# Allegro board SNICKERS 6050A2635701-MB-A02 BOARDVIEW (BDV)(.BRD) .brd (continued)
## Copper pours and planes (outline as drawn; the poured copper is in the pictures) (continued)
SD_MMC_DATA2 on BOTTOM: 299.12,73.52 299.24,73.65 299.24,74.79 298.99,75.04 297.09,75.04 296.83,74.79 296.83,73.77 297.09,73.52
SD_MMC_WP on BOTTOM (solid shape): 299.63,53.71 299.5,53.58 297.09,53.58 296.96,53.71 296.96,53.83 297.34,54.21 299.24,54.21 299.5,54.47 299.63,54.47
UIM_PWR on TOP: 257.08,80 258.99,80 259.24,79.74 259.24,78.73 258.99,78.47 258.1,78.47 257.72,78.09 257.72,75.8 257.33,75.42 255.05,75.42 254.79,75.68 254.79,76.44 255.18,76.82 255.18,79.49 255.43,79.49 255.81,79.87 256.95,79.87
UNNAMED_5_CHOKE2PIN_I90_INB on BOTTOM (solid shape): 273.84,132.57 273.84,131.56 274.61,131.56 274.61,132.57 275.5,132.57 275.75,132.32 275.75,129.02 275.37,128.64 271.18,128.64 270.8,129.02 270.8,132.19 271.56,132.95 273.46,132.95
UNNAMED_5_NMOS4D3S_I34_D0 on TOP (solid shape): 290.48,142.61 292.51,142.61 292.64,142.48 292.64,138.67 292.26,138.29 290.99,138.29 290.74,138.03 288.83,138.03 288.32,138.54 288.32,138.92 289.59,138.92 289.59,139.69 288.32,139.69 288.32,140.07 288.58,140.32 288.58,142.86 290.23,142.86
UNNAMED_7_CSC0805_I17_A on BOTTOM: 241.04,147.02 240.44,146.42 238.5,146.42 238.18,146.73 238.18,148.12 238.39,148.12 238.57,147.93 238.57,147.78 238.79,147.55 240.11,147.55 241,148.45 242.73,148.45 243.75,149.46 246.41,149.46 246.67,149.21 246.67,148.58 246.16,148.07 246.16,146.67 246.03,146.54 244.63,146.54 244.16,147.02
UNNAMED_7_CSC0805_I24_A on BOTTOM: 206.66,154.29 209.46,154.29 209.84,153.91 212.5,153.91 212.88,154.29 212.88,155.05 212.63,155.31 211.11,155.31 210.47,155.94 206.28,155.94 205.24,154.9 204.78,154.9 204.78,154.7 206.25,154.7
UNNAMED_9_AOZ1268QI02_I10_22 on BOTTOM: 154.82,162.37 154.92,162.27 154.92,161.22 154.51,161.22 154.51,158.56 154.92,158.56 154.92,157.74 155.25,157.74 155.25,158.56 155.84,158.56 155.84,161.78 155.99,161.94 155.99,163.31 155.81,163.48 146.01,163.48 145.57,163.05 145.57,161.28 145.83,161.02 146.97,161.02 147.35,160.64 151.16,160.64 151.67,161.15 151.67,161.4 152.31,162.04 153.96,162.04 154.29,162.37
UNNAMED_9_CSC0402_I67_A on BOTTOM: 176.31,152.08 177.63,152.08 177.96,151.75 178.85,151.75 179.36,151.24 179.36,150.48 179.1,150.23 178.85,150.23 178.34,150.73 177.83,150.73 177.71,150.61 176.82,150.61 176.56,150.86 176.56,151.5 176.31,151.75
UNNAMED_10_AOZ1268QI02_I13_22 on BOTTOM: 126.02,101.08 125.76,100.82 124.75,100.82 124.37,100.44 124.37,100.19 124.24,100.06 124.24,96.78 123.65,96.78 123.65,96.07 123.32,96.07 123.32,96.78 122.92,96.78 122.92,99.48 123.32,99.48 123.32,100.95 123.35,100.95 123.6,101.2 123.6,101.84 124.24,102.47 124.24,103.62 124.75,104.13 125.76,104.13 126.02,103.87
UNNAMED_11_CSC0603_I5_A on TOP (solid shape): 107.22,148.58 107.22,146.42 107.09,146.29 106.2,146.29 105.57,145.65 104.17,145.65 103.77,145.25 101.48,145.25 101.48,148.55 101.76,148.83 106.97,148.83
UNNAMED_12_CSC0603_I5_A on TOP (solid shape): 249.84,84.95 250.6,84.95 250.73,84.82 250.73,83.42 251.24,82.92 251.24,82.03 250.48,82.03 250.22,82.28 250.22,82.54 249.84,82.92 248.95,82.92 248.83,83.04 248.83,83.93 248.7,84.06 247.94,84.06 247.68,84.31 247.68,85.33 249.46,85.33
UNNAMED_14_CSD97374CQ4M_I37_4 on BOTTOM (solid shape): 235.18,69.2 235.74,69.2 235.92,69.02 235.92,67.02 235.82,66.91 234.98,66.91 234.09,66.03 233.97,66.03 233,65.06 232.39,65.06 231.81,65.64 231.81,67.25 231.97,67.41 234.23,67.41 234.23,68.05 232.06,68.05 232.06,68.06 231.81,68.31 231.81,69.33 232,69.52 234.86,69.52
UNNAMED_16_2DC3092000111F_I111_ on TOP: 316.26,148.32 316.67,147.91 316.67,141.41 316.34,141.08 314.87,141.08 314.23,141.72 313.09,141.72 312.58,141.21 307.5,141.21 307.5,142.89 307.78,142.89 308.26,143.37 308.26,145.48 309.32,146.54 311.94,146.54 312.96,147.56 315.12,147.56 315.88,148.32
UNNAMED_46_5023802471001_I1031_ on TOP (solid shape): 111.03,148.19 111.03,147.18 110.9,147.05 109.76,147.05 109.63,147.18 109.63,148.19 109.76,148.32 110.9,148.32
VADPBL on TOP (solid shape): 297.09,138.92 296.96,138.8 293.53,138.8 293.1,139.23 293.1,141.21 294.29,141.21 294.55,141.46 294.55,142.23 294.93,142.61 297.09,142.61
VRP1V2A on TOP (solid shape): 255.56,90.28 255.56,86.98 256.95,85.58 256.95,84.06 257.59,83.42 257.59,82.92 257.33,82.66 254.54,82.66 254.41,82.79 254.41,83.17 254.67,83.42 254.67,84.82 254.29,85.2 253.52,85.2 253.14,85.58 253.14,90.16 253.52,90.54 255.3,90.54
VRP1V2A_PH on TOP (solid shape): 252.13,90.16 252.13,85.58 251.75,85.2 250.1,85.2 249.97,85.33 249.97,86.6 248.95,87.62 247.68,87.62 247.68,89.39 248.83,90.54 251.75,90.54
VRP1V05A on BOTTOM: 137.07,92.7 136.94,92.57 135.8,92.57 134.91,91.68 134.27,91.68 133.89,92.06 132.75,92.06 132.49,92.31 132.49,100.19 133.13,100.82 136.94,100.82 137.07,100.7
VRP1V05A_PH on BOTTOM (solid shape): 130.33,95.74 130.08,95.49 126.02,95.49 125.64,95.87 125.38,95.87 125.33,95.92 125.33,96.68 125.13,96.89 124.64,96.89 124.64,99.86 124.82,99.86 124.82,100.24 125.66,100.24 125.66,99.71 125.56,99.6 125.56,97.7 125.74,97.52 127.16,97.52 127.79,98.16 127.79,99.55 128.81,100.57 130.33,100.57
VRP1V5S on BOTTOM (solid shape): 104.3,138.42 104.3,136.26 103.92,135.88 98.08,135.88 97.57,136.38 96.3,136.38 95.92,136.76 95.92,138.67 96.68,139.43 103.28,139.43
VRP1V5S_PH on TOP (solid shape): 99.09,148.58 99.09,146.85 99.24,146.7 99.24,145.22 96.35,145.22 95.66,145.91 95.66,148.58 95.92,148.83 98.84,148.83
VRP1V5S_PH on BOTTOM: 96.43,140.45 95.66,141.21 95.66,147.81 96.04,148.19 98.2,148.19 98.58,147.81 98.58,145.02 98.97,144.64 100.11,144.64 101.89,142.86 101.89,140.83 101.51,140.45
VRP3V3A on BOTTOM: 196.46,153.25 193.44,150.23 192.5,150.23 192.01,150.71 190.77,150.71 190.49,150.43 189.44,150.43 189.01,150.86 189.01,157.59 189.52,158.1 196.12,158.1 196.46,157.76
VRP3V3A_PH on BOTTOM: 199.28,156.83 199.28,153.2 199.58,152.89 202.22,152.89 202.98,153.66 204.4,153.66 204.4,154.54 203.11,154.54 202.22,155.43 202.22,156.58 201.71,157.08 199.53,157.08
VRP5V0A on BOTTOM: 237.27,156.45 237.27,152.54 236.96,152.24 233.05,152.24 232.57,151.75 232.57,150.23 232.32,149.97 229.01,149.97 228.81,150.17 228.81,153.23 226.09,155.95 226.09,158.54 227.11,159.56 228.33,159.56 228.93,158.95 228.93,158.92 230.54,158.92 232.25,157.21 236.89,157.21 237.27,156.83 237.27,156.45
VRP5V0A_PH on BOTTOM: 237.9,156.83 237.9,152.26 237.02,151.37 237.02,148.63 237.21,148.44 238.12,148.44 238.31,148.64 238.31,150.01 240.31,152 242.98,152 242.98,156.58 242.35,157.21 238.28,157.21
VRPVDDQ on BOTTOM (solid shape): 166.78,159.12 166.78,151.37 167.42,150.73 167.42,149.95 167.42,149.59 167.16,149.34 166.53,149.34 165.89,149.97 164.5,149.97 163.1,151.37 163.1,158.61 163.11,158.66 163.11,158.75 163.61,159.24 166.66,159.24
VRPVDDQ_PH on BOTTOM: 157.31,159.32 159.72,159.32 160.94,158.1 160.94,152.89 160.05,152 157.77,152 157,152.77 157,157.59 156.9,157.69 156.9,158.48 156.78,158.61 156.22,158.61 156.22,161.61 156.45,161.61 156.45,162.04 157.26,162.04 157.26,161.78 157.13,161.66 157.13,159.5
VRPVPACK_HG on BOTTOM (solid shape): 272.96,122.79 272.96,122.41 272.35,121.8 271.56,121.8 271.56,122.79 271.69,122.92 272.83,122.92
VRPVPACK_LG on TOP (solid shape): 286.42,125.72 285.66,124.95 285.02,124.95 285.02,125.72 285.27,125.72 285.78,126.22 285.78,126.48 286.42,126.48
VRPVPACK_PH on BOTTOM (solid shape): 269.59,125.91 275.3,125.91 275.62,125.59 275.62,119.37 275.37,119.11 274.99,119.11 274.73,119.37 273.34,119.37 272.96,119.75 272.96,122.03 273.21,122.29 273.21,122.92 272.83,123.3 271.69,123.3 271.3,122.92 271.3,121.8 269.63,121.8 269.59,121.84 269.08,121.84 268.51,122.41 268.51,125.59 268.89,125.97 269.53,125.97
VRPVTT on BOTTOM: 170.72,155.81 173.22,155.81 173.56,155.48 173.56,154.76 173.85,154.46 173.85,153.78 172.2,153.78 172.05,153.63 172.05,153.2 172.18,153.07 174.07,153.07 174.07,152.74 171.99,152.74 171.99,152.77 171.61,153.15 171.36,153.15 170.72,153.78 170.47,153.78 170.47,155.56
VRPVTT_REF on BOTTOM (solid shape): 182.91,153.66 182.91,152.26 182.79,152.13 182.53,152.13 182.02,152.64 181.64,152.64 181.52,152.77 181.52,154.54 182.02,154.54

Small or netless copper shapes (teardrops, artwork), in the pictures only: 1705 on TOP, 2506 on BOTTOM, 1708 on L3, 12 on L4, 1544 on L5, 1993 on L6

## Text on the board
Ref Des/Silkscreen Bottom: -PICKBUTTONB-A01 | 6050A2630801 | FAN | 6050A2631001 | -MIC-A01 | SPK | DIMM2 | M2X3 | HSTNN-I29C | DIMM1 | WWAN | Flash cache | WLAN | 6050A2635501-SMARTCARD-A01
Ref Des/Silkscreen Top: KB Backlit | M2x1.5 | SMART | POWER | PS | RTC | KB | FPR
User.9: HCI1005F_R12J_M | 0.1uF_16V_2_DY | short_0402_15 | 1uF_6.3V_2_DY | 680pF_50V_2_DY | 0.1uF_25V_2_DY | SFI_SFI0603_240E2R5PP_LF_2P | 0.22uF_6.3V_2 | SFI0402_050E3R0PP_LF_DY | 2.2uF_6.3V_2_DY | 0.022uF_16V_2 | 68pF_50V_2_DY | 82pF_50V_2_DY | PANASONIC_DB3X313J0L_SOT_3P | RICHTEK_RT8068AZQW_WDFN_10P | PANASONIC_DB3X313J0L_SOT_3P_DY | OSRAM_NL27WZ07DFT2G_SC88_6P | 100pF_50V_2_DY | 6.04K_1%_1/16W_2 | TSB_TC7SZ07FU_SSOP_5P | ROHM_BD82034FVJ_GE2_MSOP_8P | 18pF_50V_2_DY | 0.068uF_10V_2 | PHP_PESD5V2S2UT_SOT23_3P_DY | SFI0402_050E3R0PP_LF | 0.047uF_16V_2 | PHP_PESD5V0S1BB_SOD523_2P | EVL_12_22_Y2ST3D_C30_2C_3P | EVL_12_21_T3D_CP1Q2B12Y_2C_2P | 17.8K_1%_2 | GMT_G708T1U_SOT23_5P | LES_LBSS84LT1G_SOT23_3P | 0.1uF_16V_2 | 0.01uF_50V_2 | 1000PF_50V_2 | 100K_5%_2_DY | 10K_5%_2_DY | 1uF_6.3V_2 | CSC0402_DY | short_0402_5 | short_0603_25 | 82pF_50V_2 | 0.1uF_25V_2 | 2.2uF_6.3V_2 | 4.7uF_6.3V_3_DY | 2.2K_5%_2_DY | 8.2K_5%_2_DY | 10uF_6.3V_3_DY | 1K_1%_2_DY | 51_5%_2_DY | 47pF_50V_2 | 1K_5%_2_DY | L2N7002WT1G_DY | ON_LMV393DMR2G_SOP_8P | 10K_1%_2_DY | 68pF_50V_2 | 2200pF_50V_2 | POWERPAD1x1m | 330K_5%_2_DY | 47K_5%_2_DY | DIODE-BAT54-TAP-PHP_DY | 8.66K_1%_2 | 45.3K_1%_2 | 39.2K_1%_2 | 10pF_50V_2 | RSC_0402_DY | 3.01K_1%_2 | EVL_23_22B_Y2ST3D_C30_2T_4P | 22K_5%_2_DY | 100pF_50V_2 | 0.01uF_100V_3 | 1M_5%_2_DY | 12pF_50V_2 | 3.24K_1%_2 | 3900pF_16V_2 | 15pF_50V_2 | NUVO_NCT3521U_SOT23_5P | 57.6K_1%_2 | 31.6K_1%_2 | 0.15uF_10V_2 | 13.7K_1%_2 | 3300pF_50V_2 | ST_HP3DC2TR_LGA_16P | 53.6K_1%_2 | 16.2K_1%_2 | 41.2K_1%_2 | 51.1K_1%_2 | 38.3K_1%_2 | 46.4K_1%_2 | 35.7K_1%_2 | 4.7K_5%_2_DY | 18.2K_1%_2 | 49.9K_1%_2 | 86.6K_1%_2 | ALPHA_AO6424L_TSOP_6P | 3.48K_1%_2 | 22UF_6.3V_3_DY | PANJTT_PJSOT24C_SOT23_3P | 20K_5%_2 | 4.7K_5%_2 | 470_5%_2 | 0_5%_2_DY | 270_5%_2 | 10K_5%_2 | 10uF_6.3V_3 | 100_5%_2 | 10K_1%_2 | 15K_1%_2 | 4.7uF_6.3V_3 | 100K_5%_2 | L2N7002WT1G | 22.6_1%_2 | 8.2K_5%_2 | 22uF_6.3V_5_DY | 1.8K_1%_2 | 49.9_1%_2 | 24.9_1%_2 | L2N7002DW1T1G | 200K_5%_2 | 110_1%_2 | 150_5%_2 | 64.9_1%_2 | 0.33uF_10V_3 | POWERPAD_2_0610 | 2.2K_5%_2 | ENTERY_3703K_Q02N_11L_2P | SWF2520CF_4R7K_M | 300_5%_2 | 6.2K_1%_2 | 13K_1%_2 | 4.3K_5%_2 | REALTEK_RTS5237_GR_QFN_32P | RSC_0603_DY | 2.2uF_6.3V_3 | 22K_5%_2 | MISAKI_NTC011_BA1J_A160T_4P | HP_HPA022642RTJ_QFN_20P | BLM18PG600SN1D | 39K_1%_2 | 150_1%_2 | 2.1K_1%_2 | 619_1%_2 | 47K_5%_2 | 1.2K_1%_2 | 330_5%_2 | 470K_5%_2 | 100_1%_2 | 3.3K_5%_2 | 3.3K_1%_2 | 11K_1%_2 | 12K_1%_2 | 1uF_10V_2 | ALPHA_AON7403L_DFN_8P | TI_BQ24736RGRR_QFN_20P | 20K_1%_2 | 200K_1%_2 | 576K_1%_2 | 330K_5%_2 | 5.1K_1%_2 | 274K_1%_2 | 130K_1%_2 | 220K_5%_2 | LMBT3904LT1G | 1K_5%_2 | 33_5%_2 | 0_5%_2 | 2K_5%_2 | WCM_2012_900T | 127K_1% | 2.2uH_20% | 22uF_6.3V_5 | 2_1%_2 | 51_5%_2 | 75_1%_2 | 56_5%_2 | 62_5%_2 | AZV331KTR_E1 | DIODES_BAV99 | BAT54_30V_0.2A | INTEL_CLARKVILLE_I218_LM_48P | 30_5%_2 | BZT52-B4V7S_DY | 22_5%_2 | 10_5%_2 | 43_5%_2 | 1M_5%_2 | 1K_1%_2 | 1uF_25V_3 | 47_5%_2 | 1SS355VMTE_17 | RQ3E080BNFU7TB | REALTEK_ALC3228_CG_QFN_48P | RQ3E100BNFU7TB | PDTC144EU | ALCOR_AU9560B62_GBS_GR_SSOP_28P | TP24 | NXP_PTN3355BS_HVQFN_40P | BSS138LT1 | NRS5020T1R0NMGJ | STDPAD_3.15_5.5_TOP | SMSC_USB5534B_6080JZX_QFN_64P | PM513BA_DY | FDC638APZ | NFE31PT222Z1E9L | FIX_MASK | 100uF_6.3V | PMBT3906 | MMBT4401 | 330uF_2.5V_DY | ENTERY_6712K_F08M_02L_8P | 25MHz_10pF | BAW56S | 27MHz_10pF | 0_5%_3 | SCREW230_600_NP_1P | 10_5%_5 | SINGA_2SJ3005_023111F_7P | TP40 | ACES_50505_0064N_001_6P | BAT54C | 0.01_1%_6 | PM513BA | SCREW300_800_NP_1P | 330uF_2.5V | 100PF_3000V | 0_5%_5 | ACES_51548_01541_001_15P | B0530W_7 | ACES_50501_0184N_001_18P | 10k_5% | SINGA_2UB4006_180101F_9P | SAMTEC_BSH_030_01_L_D_A_TR_60P | BOTH_NA0069RLF_SMD_24P | TAIWIN_DP004_206CRL_TW_20P | FOX_JM3611_SP51AB11_7H_12P | ACES_51540_04041_001_40P | TAI_PMPAT3_08GLBS7N14N0_9P | ACES_51510_0344N_001_34P | SMSC_MEC1324_TQFP_128P
User.10: ROHM_BD82034FVJ_GE2_MSOP_8P | 0.1uF_16V_2_DY | 0.01uF_50V_2_DY | BLM15BB470SS1_DY | 2.2uF_6.3V_2_DY | BLM15BB470SN1D | SFI0402_050E3R0PP_LF | SFI_SFI0603_240E2R5PP_LF_2P | PHP_PESD5V0S1BB_SOD523_2P_DY | 68pF_50V_2_DY | 82pF_50V_2_DY | 10pF_50V_2_DY | short_0402_15 | 220pF_50V_2_DY | BLM15AG121SN1D_500mA | BCD_AH9249NTR_G1_TSOT23_3P | 1uF_6.3V_2_DY | SMSC_EMC1412_1_ACZL_TR_MSOP_8P | 0.1uF_25V_2_DY | SFI0402_050E3R0PP_LF_DY | 0.0015uF_50V_2 | 0.033uF_16V_2 | 0.1uF_16V_2 | 1uF_6.3V_2 | 0.01uF_50V_2 | ALPHA_AO6424L_TSOP_6P | 0.1uF_25V_2 | CSC0402_DY | short_0402_5 | 10K_5%_2_DY | 100pF_50V_2 | 8.2K_5%_2_DY | 18pF_50V_2 | 100K_5%_2_DY | 2.2uF_6.3V_2 | 4.7uF_6.3V_3_DY | 330K_5%_2_DY | 15pF_50V_2 | 1000PF_50V_2 | 2.05K_1%_2 | 3.01K_1%_2 | 10K_1%_NTC | RSC_0402_DY | 82pF_50V_2 | MXIC_MX25L1606EM2I_12G_SOP_8P_DY | 19_217_W1D_AP1Q2QY_3T | 4.7K_5%_2_DY | 68pF_50V_2 | TEXAS_TPS2546RTER_QFN_16P | 6.49K_1%_2 | 88.7K_1%_2 | ALPHA_OMEGA_AOZ1268QI_02_QFN_23P | POWERPAD_2_0610_DY | TSB_TC7SH17F_SSOP_5P | POWERPAD1x1m | GMT_G2997RE1U_TDFN_10P | POWERPAD1x1m_DY | KNOWLES_SPK0415HM4H_B_8P | 18.7K_1%_2 | 4700pF_50V_2 | 1.02M_1%_2 | 100K_1%_NTC | 9.31K_1%_2 | 220K_5%_2_DY | 4.99K_1%_2 | TI_TLV2462CDGKR_MSOP_8P | 220pF_50V_2 | 0_5%_2_DY | 10K_5%_2 | 4.7uF_6.3V_3 | L2N7002WT1G | 2.2K_5%_2 | L2N7002DW1T1G | POWERPAD_2_0610 | RSC_0603_DY | 22uF_6.3V_5_DY | 10uF_6.3V_3 | 100K_5%_2 | 33K_5%_2 | 20K_5%_2 | WINB_W25Q128FVSIQ_SOIC_8P | 470_5%_2 | 14K_1%_2 | 20K_1%_2 | 200K_5%_2 | 8.2K_5%_2 | DIODES_DMG3414U_7 | 43K_1%_2 | 330K_5%_2 | MPS_NB670GQ_QFN_16P | 0.22uF_25V_3 | 10K_1%_2 | 1uF_10V_2 | MISAKI_NTC011_BA1J_A160T_4P | 4.7K_5%_2 | 100_5%_2 | BLM18PG600SN1D | 5.1M_5%_2 | 12K_5%_DY | 470K_5%_2 | 220_5%_2 | 47K_5%_2 | 3.3K_5%_2 | 64.9_1%_2 | 680_5%_2 | 10M_5%_2 | 24.9_1%_2 | 2.2uF_10V_3 | 100_1%_2 | 200_1%_2 | 120_1%_2 | 39K_1%_2 | 2.32K_1% | 54.9_1%_2 | 432K_1%_2 | TEXAS_TPS51622ARSMR_VQFN_32P | 100K_1%_2 | 110_1%_2 | 150K_1%_2 | TI_CSD97374CQ4M_SON_8P | MPS_NB676AGQ_QFN_16P | 22UF_6.3V_3 | 0_5%_2 | 22_5%_2 | 47_5%_2 | 2.2_5%_3 | 10UF_25V_5 | 22uF_6.3V_5 | 1K_5%_2 | 15_5%_2 | 1M_5%_2 | 33_5%_2 | 2.2uH_20% | LMBT3904LT1G | WINBOND_W25Q16DVSSIG_8P | 10_5%_2 | STDPAD_3.15_5.5_TOP | CSC0805_DY | TC7SZ08FU | 1uF_25V_3 | RQ3E100BNFU7TB | RQ3E150BNFU7TB | 3K_1%_2 | 4.7uF_25V_5 | DIODES_BAV99 | WCM_2012_900T | FDC638APZ_DY | INFINEON_SLB9660TT1_2_TSSOP_28P | TP24 | ACES_50376_01001_001_10P | NRS5020T1R0NMGJ | PARADE_PS8338AQFN60GTR_QFN_60P | SCREW280_500_NP_1P | FIX_MASK | SCREW230_600_NP_1P | PAN_ETQP3W1R0WFN_4P | STDPAD_1.15_6-TOP | SCREW230_500_1P | 24MHz_12pF | SCREW300_800_NP_1P | FDMC7692S | ACES_91960_0084L_8P | SCREW330_600_1P | PCME063T-R24MS1R195 | SCREW230_600_1P | FDMC8884 | PM514BA | ACES_50271_0040N_001_4P | BAT54C | SCREW360_800_NP_1P | 0_5%_5 | 0.02_1%_6 | SCREW300_800_1P | SCREW360_800_1P | PCMC063T-1R5MN | 15uF_25V | ACES_50238_02471_001_24P | SINGA_2DC3092_000111F_9P | ETQP3W4R7WFN | ALLTOP_C11848_122A1_L_22P | FOX_BP02083_B24B1_9H_8P | FOX_AS0A626_U4R6_7H_HP_204P | 32.768KHZ | 100uF_6.3V | INTEL_CL8064701477702_SR170_1168P | SYN_070546HR015M22BZR_15P | HAMB_083AA24F08B_10P | ACES_59003_04006_001_40P | LOTES_APCI0018_P005A_75P | LOTES_APCI0020_P001A01_75P | FOXCONN_AS0BC26_S30BE_7H_75P | FULLINHOPE_A0131_0001_12P | FOX_QL1046L_D262AR_7H_92P
User.45: FIGURE | SIZE | 10.0 | 12.0 | 16.0 | 20.0 | 24.0 | 27.0 | 28.0 | 31.0 | 35.0 | 39.0 | 45.0 | 91.0 | 118.0 | 124.0 | 130.0 | 142.0 | 25.0 | 33.0 | 40.0 | 43.0 | 46.0 | 49.0 | 51.0 | 63.0 | 110.0 | 158.0 | 45.0x26.0 | 47.0x28.0 | 55.0x26.0 | 63.0x16.0 | 63.0x24.0 | 67.0x28.0 | 73.0x31.0 | 79.0x24.0 | 83.0x28.0 | 87.0x20.0 | 94.0x24.0 | 100.0x28.0 | 102.0x31.0 | 106.0x39.0 | 63.0x51.0 | 87.0x79.0 | 157.0x79.0 | DRILL CHART: TOP to BOTTOM | ALL UNITS ARE IN MILS | PLATED | NON-PLATED | QTY | 4269 | 4 | 2 | 328 | 46 | 20 | 22 | 42 | 8 | 3 | 1 | 19 | 6 | 5 | 10 | 7
